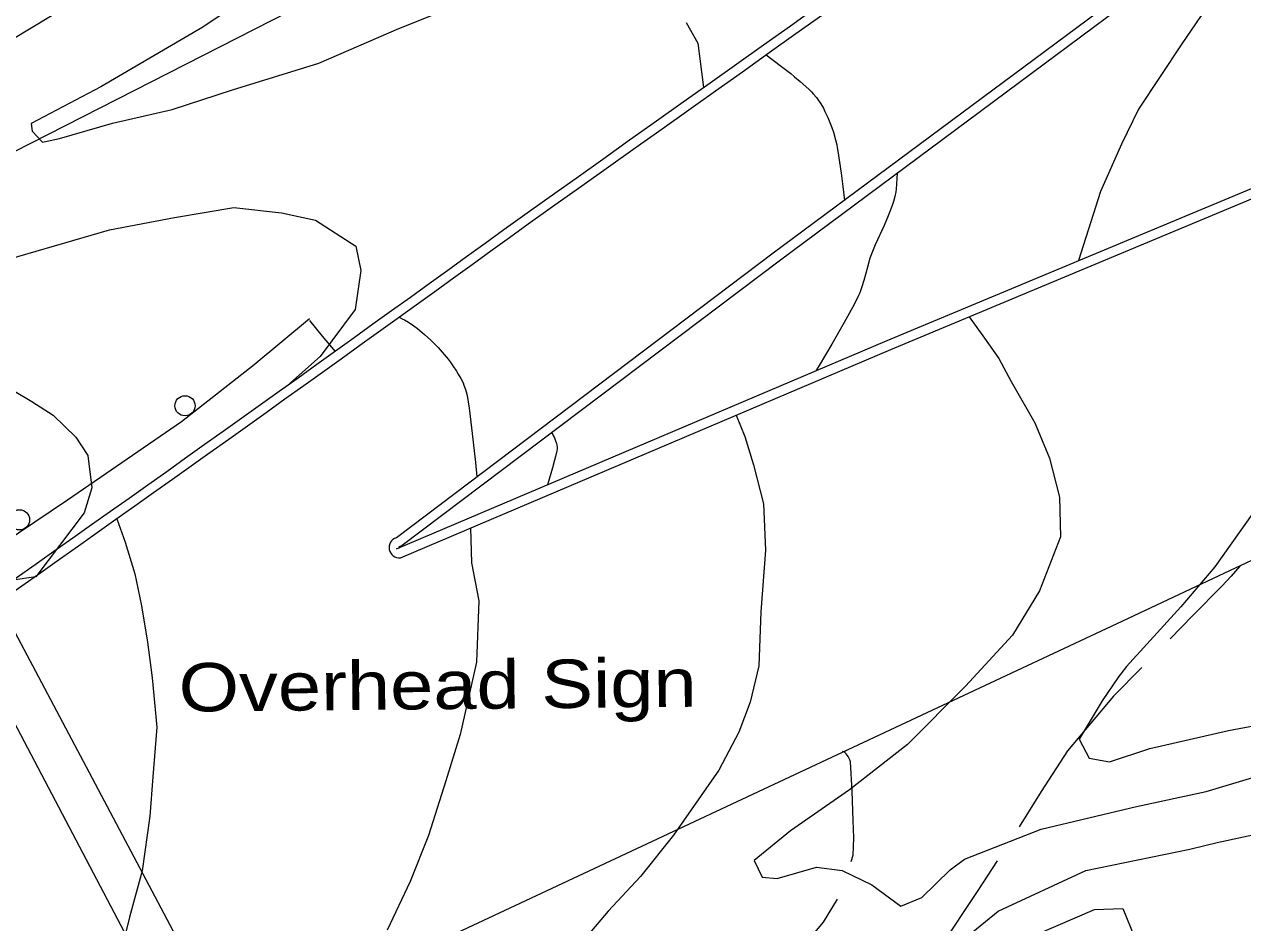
# Model space of a CAD drawing. Extents: x 2361284 to 2366480, y 6976556 to 6985346.
# Drawn here: x 2363734.5 to 2363855.4, y 6978563.7 to 6978652.7 of the extents above; entities that cross this region are included whole.
import ezdxf

# ---------------------------------------------------------------- set-up
doc = ezdxf.new("R2010")
doc.units = 0
doc.header["$LTSCALE"] = 1.9
for name, color, linetype, lineweight in [('10', 7, 'Continuous', 13), ('12', 7, 'Continuous', 13), ('13', 7, 'Continuous', 13), ('15', 7, 'Continuous', 13), ('17', 7, 'Continuous', 13), ('21', 7, 'Continuous', 13), ('3', 7, 'Continuous', 13), ('5', 7, 'Continuous', 13)]:
    doc.layers.add(name, color=color, linetype=linetype, lineweight=lineweight)

msp = doc.modelspace()

# ---------------------------------------------------------------- linework, layer by layer
at = {"layer": '10'}
msp.add_lwpolyline([(2363724.56, 6978600.493), (2363728.231, 6978602.487), (2363761.061, 6978540.617), (2363757.15, 6978538.549)], close=True, dxfattribs=at)
at = {"layer": '12'}
for points in [[(2363953.807, 6978799.854), (2363950.815, 6978797.905), (2363947.317, 6978795.582), (2363942.293, 6978791.664), (2363931.416, 6978784.08), (2363923.864, 6978778.927), (2363914.944, 6978772.552), (2363906.78, 6978766.615), (2363901.761, 6978763.447), (2363888.789, 6978754.992), (2363882.411, 6978750.582), (2363870.653, 6978742.96), (2363862.704, 6978737.524), (2363850.232, 6978729.145), (2363836.706, 6978719.346), (2363825.404, 6978712.048), (2363814.472, 6978704.934), (2363799.243, 6978694.177), (2363787.31, 6978685.994), (2363777.501, 6978679.511), (2363766.917, 6978672.43), (2363754.892, 6978664.634), (2363741.451, 6978656.097), (2363729.092, 6978648.638)], [(2363727.011, 6978627.768), (2363730.223, 6978628.629), (2363742.967, 6978632.329), (2363749.437, 6978633.541), (2363755.318, 6978634.527), (2363760.053, 6978634.022), (2363763.42, 6978633.294), (2363767.424, 6978630.712), (2363767.907, 6978628.297), (2363767.363, 6978624.441), (2363763.879, 6978619.768), (2363760.626, 6978616.907)], [(2363743.7, 6978603.684), (2363744.542, 6978601.373), (2363745.482, 6978598.212), (2363746.163, 6978595.038), (2363746.767, 6978591.464), (2363747.2, 6978587.928), (2363747.667, 6978583.031), (2363747.294, 6978578.097), (2363746.971, 6978574.195), (2363746.222, 6978568.788), (2363744.965, 6978564.205), (2363743.636, 6978558.841), (2363743.552, 6978556.131), (2363743.197, 6978553.437), (2363742.035, 6978550.476), (2363740.497, 6978548.151), (2363738.588, 6978545.034), (2363736.921, 6978540.478), (2363735.95, 6978538.517), (2363734.922, 6978536.178), (2363732.996, 6978533.639)]]:
    msp.add_lwpolyline(points, dxfattribs=at)
at = {"layer": '13'}
for points in [[(2363949.721, 6978718.44), (2363945.915, 6978715.914), (2363942.693, 6978713.883), (2363936.084, 6978709.54), (2363927.472, 6978704.538), (2363922.188, 6978701.668), (2363914.098, 6978697.45), (2363904.199, 6978691.075), (2363897.733, 6978686.254), (2363889.209, 6978681.383), (2363882.648, 6978677.331), (2363871.019, 6978669.749), (2363866.581, 6978666.376), (2363862.183, 6978662.984), (2363855.502, 6978658.722), (2363851.172, 6978653.48), (2363849.339, 6978650.763), (2363845.02, 6978644.28), (2363843.343, 6978640.804), (2363841.267, 6978636.124), (2363839.093, 6978629.274)], [(2363762.87, 6978659.57), (2363752.238, 6978652.419), (2363742.113, 6978646.482), (2363735.218, 6978642.846), (2363735.315, 6978642.117), (2363736.335, 6978640.997), (2363738.022, 6978641.363), (2363743.277, 6978642.883), (2363749.195, 6978644.249), (2363755.197, 6978646.196), (2363763.742, 6978648.848), (2363771.69, 6978652.284), (2363779.201, 6978655.326)], [(2363800.175, 6978652.875), (2363801.325, 6978650.816), (2363801.897, 6978646.44)], [(2363808.096, 6978649.659), (2363808.655, 6978649.251), (2363809.758, 6978648.415), (2363810.538, 6978647.805), (2363810.922, 6978647.494), (2363811.49, 6978647.016), (2363812.329, 6978646.27), (2363812.602, 6978646.003), (2363812.774, 6978645.818), (2363813.096, 6978645.429), (2363813.246, 6978645.226), (2363813.527, 6978644.806), (2363813.783, 6978644.368), (2363813.94, 6978644.067), (2363814.227, 6978643.447), (2363814.488, 6978642.801), (2363814.608, 6978642.477), (2363814.773, 6978641.988), (2363814.985, 6978641.248), (2363815.102, 6978640.749), (2363815.153, 6978640.497), (2363815.218, 6978640.117), (2363815.541, 6978637.954), (2363815.685, 6978636.871), (2363815.811, 6978635.787), (2363815.865, 6978635.243)], [(2363821.099, 6978637.943), (2363821.042, 6978636.875), (2363820.995, 6978636.341), (2363820.964, 6978636.097), (2363820.869, 6978635.615), (2363820.739, 6978635.14), (2363820.638, 6978634.827), (2363820.415, 6978634.206), (2363820.222, 6978633.712), (2363819.802, 6978632.741), (2363818.926, 6978630.822), (2363818.654, 6978630.176), (2363818.526, 6978629.849), (2363818.371, 6978629.406), (2363818.278, 6978629.107), (2363818.109, 6978628.501), (2363817.787, 6978627.284), (2363817.605, 6978626.683), (2363817.39, 6978626.094), (2363817.265, 6978625.806), (2363816.825, 6978624.906), (2363816.513, 6978624.316), (2363815.86, 6978623.152), (2363814.623, 6978621.001), (2363813.995, 6978619.932), (2363813.353, 6978618.871), (2363813.025, 6978618.345)], [(2363771.702, 6978623.672), (2363772.022, 6978623.509), (2363772.228, 6978623.397), (2363772.622, 6978623.166), (2363773.181, 6978622.794), (2363773.539, 6978622.529), (2363773.773, 6978622.343), (2363774.238, 6978621.946), (2363774.852, 6978621.381), (2363775.146, 6978621.094), (2363775.571, 6978620.654), (2363775.98, 6978620.201), (2363776.179, 6978619.968), (2363776.565, 6978619.487), (2363776.753, 6978619.238), (2363777.028, 6978618.853), (2363777.4, 6978618.3), (2363777.576, 6978618.02), (2363777.823, 6978617.594), (2363778.042, 6978617.159), (2363778.139, 6978616.937), (2363778.304, 6978616.484), (2363778.37, 6978616.252), (2363778.446, 6978615.896), (2363778.644, 6978614.643), (2363778.76, 6978613.807), (2363778.962, 6978612.131), (2363779.278, 6978609.268), (2363779.423, 6978607.835)], [(2363828.224, 6978623.7), (2363829.774, 6978621.584), (2363831.183, 6978619.568), (2363832.405, 6978617.299), (2363834.745, 6978613.181), (2363836.219, 6978609.675), (2363837.205, 6978605.833), (2363837.303, 6978601.885), (2363835.224, 6978596.525), (2363832.524, 6978592.139), (2363827.862, 6978587.085), (2363822.128, 6978581.309), (2363816.38, 6978576.824), (2363810.508, 6978572.739), (2363806.925, 6978569.815), (2363807.721, 6978568.152), (2363809.203, 6978568.016), (2363813.113, 6978569.154), (2363815.646, 6978568.828), (2363818.59, 6978567.386), (2363821.45, 6978565.293), (2363823.558, 6978566.133), (2363826.367, 6978568.903), (2363827.775, 6978569.933), (2363835.368, 6978572.905), (2363844.827, 6978575.164), (2363851.742, 6978576.65), (2363863.54, 6978580.202)], [(2363733.57, 6978616.329), (2363735.29, 6978615.306), (2363737.392, 6978613.966), (2363739.642, 6978611.767), (2363740.82, 6978609.948), (2363741.23, 6978606.752), (2363740.484, 6978604.274), (2363735.679, 6978597.915), (2363733.388, 6978597.587)], [(2363805.126, 6978613.95), (2363805.976, 6978611.848), (2363806.863, 6978609.016), (2363807.849, 6978605.174), (2363808.043, 6978600.567), (2363807.571, 6978594.472), (2363807.382, 6978589.12), (2363806.506, 6978585.521), (2363805.405, 6978582.52), (2363803.4, 6978578.771), (2363798.921, 6978572.309), (2363795.63, 6978568.237), (2363792.444, 6978564.777), (2363790.416, 6978562.427)], [(2363786.841, 6978612.226), (2363787.032, 6978611.869), (2363787.118, 6978611.69), (2363787.229, 6978611.421), (2363787.313, 6978611.152), (2363787.342, 6978611.017), (2363787.369, 6978610.748), (2363787.367, 6978610.613), (2363787.339, 6978610.41), (2363787.212, 6978609.855), (2363787.118, 6978609.485), (2363786.914, 6978608.746), (2363786.59, 6978607.62), (2363786.42, 6978607.061)], [(2363857.417, 6978605.735), (2363852.611, 6978598.92), (2363849.229, 6978594.958), (2363843.835, 6978589.047), (2363843.065, 6978588.019), (2363841.447, 6978585.644), (2363839.143, 6978581.851), (2363840.142, 6978579.94), (2363842.142, 6978579.597), (2363846.143, 6978580.907), (2363853.955, 6978582.711), (2363864.727, 6978584.705)], [(2363778.791, 6978602.778), (2363778.874, 6978599.329), (2363779.619, 6978595.566), (2363779.377, 6978589.474), (2363777.745, 6978582.307), (2363776.329, 6978577.723), (2363774.611, 6978572.278), (2363772.794, 6978567.72), (2363770.509, 6978562.918)], [(2363823.761, 6978558.813), (2363831.114, 6978564.804), (2363839.807, 6978568.827), (2363850.128, 6978570.946), (2363852.83, 6978571.611), (2363858.53, 6978572.806)], [(2363834.917, 6978562.471), (2363840.654, 6978564.945), (2363843.473, 6978565.042), (2363844.64, 6978562.203)]]:
    msp.add_lwpolyline(points, dxfattribs=at)
at = {"layer": '15'}
for points in [[(2363855.09, 6978598.994), (2363854.21, 6978597.986), (2363853.299, 6978596.997), (2363850.438, 6978594.08), (2363848.159, 6978591.788)], [(2363845.356, 6978588.941), (2363842.563, 6978586.094), (2363837.995, 6978580.67), (2363835.393, 6978576.645), (2363833.215, 6978573.135)], [(2363816.548, 6978569.706), (2363816.742, 6978570.338), (2363816.806, 6978572.059), (2363816.739, 6978573.788), (2363816.651, 6978576.697), (2363816.464, 6978579.605), (2363816.422, 6978579.774), (2363816.229, 6978580.133), (2363816.046, 6978580.381), (2363815.905, 6978580.53), (2363815.814, 6978580.599), (2363815.714, 6978580.628), (2363815.674, 6978580.597), (2363815.665, 6978580.527)], [(2363831.027, 6978569.784), (2363829.095, 6978566.835), (2363825.309, 6978561.108), (2363822.056, 6978556.287), (2363819.774, 6978553.255)], [(2363802.478, 6978550.571), (2363803.943, 6978552.135), (2363808.949, 6978557.882), (2363813.805, 6978563.7), (2363815.173, 6978565.973)]]:
    msp.add_lwpolyline(points, dxfattribs=at)
at = {"layer": '17'}
msp.add_lwpolyline([(2363604.376, 6978528.616), (2363609.017, 6978530.66), (2363613.588, 6978532.794), (2363618.127, 6978535.007), (2363622.665, 6978537.29), (2363627.133, 6978539.664), (2363629.251, 6978540.824), (2363650.526, 6978552.126), (2363671.415, 6978563.846), (2363692.121, 6978575.932), (2363699.589, 6978580.344), (2363712.882, 6978588.501), (2363725.914, 6978596.916), (2363738.811, 6978605.558), (2363750.119, 6978613.337), (2363757.336, 6978618.985), (2363762.813, 6978623.528)], dxfattribs=at)
for centre in [(2363750.472, 6978614.883), (2363734.065, 6978603.58)]:
    msp.add_circle(centre, 1, dxfattribs=at)
at = {"layer": '21'}
msp.add_lwpolyline([(2363785.053, 6978666.711), (2363774.378, 6978660.899), (2363731.753, 6978639.173)], dxfattribs=at)
at = {"layer": '3'}
for p, q in [((2363783.931, 6978633.682), (2363783.94, 6978633.688)), ((2363784.495, 6978632.904), (2363784.495, 6978632.905))]:
    msp.add_line(p, q, dxfattribs=at)
for points in [[(2363771.738, 6978600.776), (2363771.45, 6978600.709), (2363820.107, 6978621.352), (2363862.431, 6978639.006), (2363943.048, 6978676.525)], [(2363771.829, 6978599.821), (2363771.828, 6978599.822), (2363820.475, 6978620.466), (2363862.819, 6978638.129), (2363943.456, 6978675.659)], [(2363851.335, 6978661.611), (2363808.803, 6978629.996), (2363771.43, 6978601.809), (2363771.43, 6978601.809)], [(2363851.912, 6978660.837), (2363809.381, 6978629.232), (2363772.007, 6978601.044), (2363771.715, 6978600.892)], [(2363938.462, 6978638.188), (2363842.885, 6978593.258), (2363745.482, 6978547.689), (2363698.71, 6978525.581), (2363675.402, 6978514.362), (2363652.17, 6978502.987), (2363640.587, 6978497.229), (2363599.569, 6978476.516), (2363572.307, 6978462.546), (2363517.928, 6978434.329), (2363417.601, 6978381.942), (2363311.373, 6978326.429), (2363206.577, 6978271.789), (2363109.125, 6978220.97)]]:
    msp.add_lwpolyline(points, dxfattribs=at)
for centre, radius, start, end in [((2361861.142, 6981945.89), 3737.254, 298.19355, 302.82403), ((2353709.947, 6992844.372), 17419.21, 305.33293, 306.01888), ((2353709.947, 6992844.372), 17420.17, 305.33293, 306.01888), ((2361121.949, 6982307.802), 4537.104, 304.07791, 305.92417), ((2361121.949, 6982307.802), 4538.064, 304.07791, 305.92417), ((2363771.733, 6978600.835), 1.019, 107.29477, 275.40685), ((2363771.733, 6978600.835), 0.0593, 107.29488, 275.40696)]:
    msp.add_arc(centre, radius, start, end, dxfattribs=at)
at = {"layer": '5'}
msp.add_lwpolyline([(2363762.813, 6978623.329), (2363764.078, 6978621.793), (2363765.35, 6978620.25)], dxfattribs=at)

# ---------------------------------------------------------------- texts
at = {"layer": '10', "width": 1.2}
msp.add_text('Overhead Sign', height=4.799, rotation=0.545, dxfattribs=at).set_placement((2363749.863, 6978584.563))

doc.saveas('drawing.dxf')
